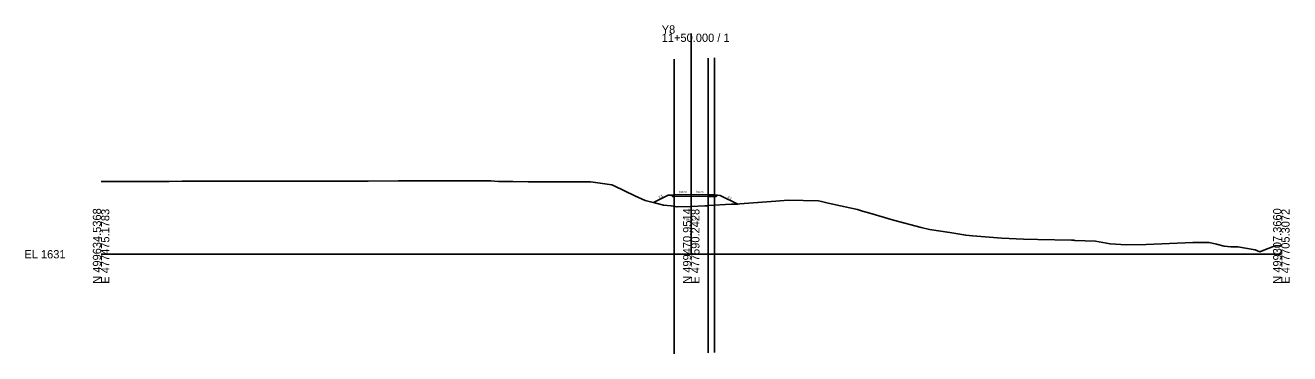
# Model space of a CAD drawing. Extents: x -26 to 403, y -10 to 2517.
# Drawn here: x -25.7 to 402.8, y 1466.2 to 1577.7 of the extents above; entities that cross this region are included whole.
import ezdxf

# ---------------------------------------------------------------- set-up
doc = ezdxf.new("R2010")
doc.units = 0
for name, color, linetype in [('Exist Cross Section Cell', 7, 'Continuous'), ('Exist XS Center Line Elevation Label', 7, 'Continuous'), ('Exist XS Ground Line', 7, 'Continuous'), ('Prop Road Sect_ Boring - Material (Outline)', 7, 'Continuous'), ('Prop XS Dump Level', 7, 'Continuous'), ('Prop XS Earthwork Shape', 7, 'Continuous'), ('Prop XS EOT Tick Mark', 7, 'Continuous'), ('Prop XS Finish Grade', 7, 'Continuous'), ('Prop XS Finish Grade Earthwork', 7, 'Continuous'), ('Prop XS Finish Grade Paved Shoulder', 7, 'Continuous'), ('Prop XS Finish Grade Pavement', 7, 'Continuous'), ('Prop XS Pvmt Edge Slope', 7, 'Continuous'), ('Prop XS SE Text', 7, 'Continuous'), ('Prop XS Side Slope Text', 7, 'Continuous'), ('Prop XS Subgrade Earthwork', 7, 'Continuous'), ('Scratch_Level_5', 7, 'Continuous')]:
    doc.layers.add(name, color=color, linetype=linetype)

msp = doc.modelspace()

# ---------------------------------------------------------------- linework, layer by layer
at = {"layer": 'Exist Cross Section Cell'}
for p, q in [((200, 1500), (200, 1574.87)), ((0, 1500), (200, 1500)), ((200, 1500), (400, 1500))]:
    msp.add_line(p, q, dxfattribs=at)
at = {"layer": 'Exist XS Ground Line'}
msp.add_lwpolyline([(0, 1524.66), (2.01, 1524.68), (3.61, 1524.65), (4.82, 1524.65), (23.03, 1524.74), (27.49, 1524.75), (46.34, 1524.85), (55.36, 1524.86), (58.52, 1524.86), (72.49, 1524.84), (83.08, 1524.83), (90.55, 1524.86), (100.85, 1524.92), (102.91, 1524.91), (106.53, 1524.96), (118.88, 1524.89), (132.06, 1524.93), (133.38, 1524.85), (134.64, 1524.71), (139.54, 1524.68), (144.79, 1524.54), (164.03, 1524.57), (165.89, 1524.58), (166.75, 1524.48), (173.07, 1523.59), (173.91, 1523.25), (180.91, 1519.79), (184.37, 1518.21), (190.66, 1516.71), (193.22, 1516.43), (195.23, 1516.07), (200, 1516.25), (204.65, 1516.44), (205.3, 1516.47), (205.68, 1516.57), (213.7, 1517), (214.92, 1516.97), (228.67, 1518.05), (232.87, 1518.36), (243.14, 1518.1), (244.12, 1517.96), (246.45, 1517.39), (256.35, 1515.15), (258.07, 1514.64), (260.52, 1513.93), (268.58, 1511.61), (277.91, 1509.13), (280.8, 1508.43), (287.68, 1507.36), (293.03, 1506.46), (295.29, 1506.3), (305.26, 1505.47), (312.67, 1505.18), (317.49, 1505.06), (328.91, 1504.74), (329.72, 1504.73), (330.06, 1504.72), (337.04, 1504.39), (341.95, 1503.52), (347.44, 1503.25), (354.18, 1503.35), (369.96, 1503.94), (375.59, 1503.95), (378.08, 1503.46), (380.67, 1502.71), (382.88, 1502.53), (385.25, 1502.51), (391.09, 1501.55), (392.66, 1500.82), (394.62, 1501.59), (397.92, 1502.85), (400, 1502.99)], dxfattribs=at)
at = {"layer": 'Prop Road Sect_ Boring - Material (Outline)'}
for points in [[(194.24, 1520.19), (193.68, 1519.64), (193.21, 1520.11)], [(194.24, 1520.19), (193.68, 1519.64), (193.21, 1520.11)], [(208.39, 1519.6), (208.87, 1520.07), (207.84, 1520.15)], [(208.39, 1519.6), (208.87, 1520.07), (207.84, 1520.15)]]:
    msp.add_lwpolyline(points, close=True, dxfattribs=at)
at = {"layer": 'Prop XS Dump Level'}
for p, q in [((194.24, 1520.19), (200, 1520.31)), ((200, 1520.31), (205.76, 1520.19))]:
    msp.add_line(p, q, dxfattribs=at)
at = {"layer": 'Prop XS Earthwork Shape'}
msp.add_lwpolyline([(187.22, 1517.53), (190.66, 1516.71), (193.22, 1516.43), (195.23, 1516.07), (200, 1516.25), (204.65, 1516.44), (205.3, 1516.47), (205.68, 1516.57), (213.7, 1517), (214.92, 1516.97), (215.78, 1517.04), (209.84, 1519.99), (208.87, 1520.07), (208.39, 1519.6), (207.84, 1519.61), (205.76, 1519.65), (200, 1519.77), (194.24, 1519.65), (193.68, 1519.64), (193.21, 1520.11), (192.23, 1520.03)], close=True, dxfattribs=at)
at = {"layer": 'Prop XS EOT Tick Mark'}
for p, q in [((194.24, 1520.19), (194.24, 1521.19)), ((205.76, 1520.19), (205.76, 1521.19))]:
    msp.add_line(p, q, dxfattribs=at)
at = {"layer": 'Prop XS Finish Grade'}
for p, q in [((194.24, 1520.19), (193.21, 1520.11)), ((207.84, 1520.15), (208.87, 1520.07))]:
    msp.add_line(p, q, dxfattribs=at)
at = {"layer": 'Prop XS Finish Grade Earthwork'}
for p, q in [((192.23, 1520.03), (187.22, 1517.53)), ((193.21, 1520.11), (192.23, 1520.03)), ((208.87, 1520.07), (209.84, 1519.99)), ((209.84, 1519.99), (215.78, 1517.04))]:
    msp.add_line(p, q, dxfattribs=at)
at = {"layer": 'Prop XS Finish Grade Paved Shoulder'}
msp.add_line((205.76, 1520.19), (207.84, 1520.15), dxfattribs=at)
at = {"layer": 'Prop XS Finish Grade Pavement'}
for p, q in [((194.24, 1520.19), (200, 1520.31)), ((200, 1520.31), (205.76, 1520.19))]:
    msp.add_line(p, q, dxfattribs=at)
at = {"layer": 'Prop XS Pvmt Edge Slope'}
for p, q in [((194.24, 1520.19), (193.68, 1519.64)), ((207.84, 1520.15), (208.39, 1519.6))]:
    msp.add_line(p, q, dxfattribs=at)
at = {"layer": 'Prop XS Subgrade Earthwork'}
for p, q in [((193.68, 1519.64), (193.21, 1520.11)), ((194.24, 1519.65), (193.68, 1519.64)), ((200, 1519.77), (194.24, 1519.65)), ((205.76, 1519.65), (200, 1519.77)), ((205.76, 1519.65), (207.84, 1519.61)), ((207.84, 1519.61), (208.39, 1519.6)), ((208.39, 1519.6), (208.87, 1520.07))]:
    msp.add_line(p, q, dxfattribs=at)
at = {"layer": 'Scratch_Level_5'}
for p, q in [((194.24, 1566.25), (194.24, 1466.25)), ((205.76, 1566.58), (205.76, 1466.58)), ((207.84, 1566.69), (207.84, 1466.69))]:
    msp.add_line(p, q, dxfattribs=at)

# ---------------------------------------------------------------- texts
at = {"layer": 'Exist Cross Section Cell'}
for s, p in [('Y8', (190, 1574.87)), ('11+50.000 / 1', (190, 1572.07)), ('EL 1631', (-26, 1498.6))]:
    msp.add_text(s, height=2.8, dxfattribs=at).set_placement(p)
for s, p in [('N 499634.5368', (0, 1490)), ('E 477475.1783', (2.8, 1490)), ('N 499470.9514', (200, 1490)), ('E 477590.2428', (202.8, 1490)), ('N 499307.3660', (400, 1490)), ('E 477705.3072', (402.8, 1490))]:
    msp.add_text(s, height=2.8, rotation=90, dxfattribs=at).set_placement(p)
at = {"layer": 'Exist XS Center Line Elevation Label'}
msp.add_text('1647.25', height=0.9, dxfattribs=at).set_placement((197.95, 1511.35))
at = {"layer": 'Prop XS Dump Level'}
for p in [(192.23, 1519.99), (208.78, 1519.91)]:
    msp.add_text('Case1', height=0.04, dxfattribs=at).set_placement(p)
at = {"layer": 'Prop XS SE Text'}
for rotation, p in [(1.1458, (195.85, 1520.72)), (358.8542, (201.61, 1520.78))]:
    msp.add_text('0.020', height=0.75, rotation=rotation, dxfattribs=at).set_placement(p)
at = {"layer": 'Prop XS Side Slope Text'}
for rotation, p in [(26.5651, (189.19, 1519)), (333.5604, (212.28, 1519.21))]:
    msp.add_text('2:1', height=0.75, rotation=rotation, dxfattribs=at).set_placement(p)

doc.saveas('drawing.dxf')
